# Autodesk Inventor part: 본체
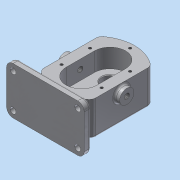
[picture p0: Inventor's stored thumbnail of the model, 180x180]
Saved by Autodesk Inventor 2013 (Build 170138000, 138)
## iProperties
Created: 2019-03
Part Number: 본체
Material: 알루미늄 6061
Document SubType Name: Modeling
Designer: dgall
Density: 1 g/cm^3
Author: dgall
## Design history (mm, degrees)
sketch "스케치1"
  geometry: L1 (-40, -15.279)-(-40, -104.721); L2 (40, -15.279)-(40, -104.721); A1 r 60 centre (0, -60) between (40, -15.279) and (-40, -15.279); A2 r 60 centre (0, -60) between (-40, -104.721) and (40, -104.721); 1 further point
  constraints: 6 point on circle, 4 end point, 2 centre point, 1 coincident, 1 concentric, 1 parallel, 1 vertical, 1 vertical alignment
  dimensions: "d5" = 60 radius of A1; "d7" = 80 distance between parallel lines of L2 L1
extrude "돌출1" new body sketch "스케치1" stored distance "d8" = 53; taper "d9" = 0 deg
sketch "스케치2"
  geometry: L1 (40, -104.721)-(40, -15.279) reference; L2 (-24, -38)-(-24, -82); L3 (24, -38)-(24, -82); A1 r 60 centre (0, -60) between (40, -15.279) and (-40, -15.279) reference; A2 r 24 centre (0, -38) between (24, -38) and (-24, -38); A3 r 24 centre (0, -82) between (-24, -82) and (24, -82); 1 further point
  constraints: 4 end point, 4 point on circle, 3 vertical alignment, 2 centre point, 2 tangent, 1 equal radius, 1 parallel, 1 vertical
  dimensions: "d10" = 24 radius of A2; "d12" = 22 distance of A2.centre A1.centre; "d13" = 22 distance of A3.centre A1.centre
extrude "돌출2" cut sketch "스케치2" distance "d14" = 29; taper "d15" = 0 deg
sketch "스케치3"
  geometry: C1 r 19 at (0, -38); A1 r 60 centre (0, -60) between (40, -15.279) and (-40, -15.279) reference; 1 further point
  constraints: 1 centre point, 1 vertical alignment
  dimensions: "d16" = 38 diameter of C1; "d17" = 22 distance of A1.centre C1.centre
extrude "돌출3" join sketch "스케치3" distance "d18" = 17; taper "d19" = 0 deg
sketch "스케치4"
  geometry: L1 (-14, -2.5)-(-14, 26.5) reference; L2 (-14, 26.5)-(0, 26.5) reference; L3 (0, 26.5)-(0, -26.5) reference; L4 (0, -26.5)-(-19, -26.5) reference; L5 (-19, -26.5)-(-19, -43.5) reference; L6 (-19, -43.5)-(-57, -43.5) reference; L7 (-57, -43.5)-(-57, -26.5) reference; L8 (-57, -26.5)-(-120, -26.5) reference; L9 (-120, -26.5)-(-120, 26.5) reference; L10 (-120, 26.5)-(-106, 26.5) reference; L11 (-106, 26.5)-(-106, -2.5) reference; L12 (-106, -2.5)-(-14, -2.5) reference; L13 (-38, -2.5)-(-14, -2.5) reference; L14 (-38, -2.5)-(-38, -43.5); L15 (-25.5, -2.5)-(-25.5, -17.5); L16 (-25.5, -17.5)-(-29.5, -17.5); L17 (-29.5, -17.5)-(-29.5, -36.2); L18 (-29.5, -36.2)-(-24, -36.2); L19 (-24, -36.2)-(-24, -43.5); 1 further point
  constraints: 12 end point, 4 perpendicular, 3 point on line, 2 parallel, 1 midpoint
  dimensions: "d20" = 19 distance from line of L14.end L5; "d22" = 25 diameter of L15 L14; "d23" = 17 diameter of L17 L14; "d24" = 28 diameter of L19 L14; "d25" = 15 distance of L15.start L15.end; "d26" = 7.3 distance of L18.end L19.end
revolve "회전1" sketch "스케치4" stored, may be unused: angle "d27" = 90 deg
sketch "스케치5"
  geometry: C1 r 12.5 at (0, -82); A1 r 24 centre (0, -82) between (-24, -82) and (24, -82) reference; 1 further point
  constraints: 1 centre point, 1 coincident
  dimensions: "d30" = 25 diameter of C1
extrude "돌출4" cut sketch "스케치5" distance "d32" = 15; taper "d33" = 0 deg
sketch "스케치6"
  geometry: L1 (0, 0)-(0, 89.443) reference; L2 (70, 47.721)-(70, 85.721) reference; L3 (70, 66.721)-(0, 66.721); L4 (0, 66.721)-(29, 66.721) reference; C1 r 11 at (14, 44.721); 1 further point
  constraints: 2 end point, 1 centre point, 1 collinear, 1 midpoint
  dimensions: "d34" = 22 diameter of C1; "d36" = 14 distance from line of C1.centre L1; "d37" = 22 distance from line of C1.centre L3
extrude "돌출5" join sketch "스케치6" distance "d38" = 8; taper "d39" = 0 deg
node "작업 평면1"
hole "구멍1" diameter "d42" = 8.376; stored, may be unused: countersink angle "d46" = 90 deg, drill point angle "d48" = 118 deg; dims "d40" = 10, "d41" = 10, "d43" = 6, "d44" = 4, "d45" = 2, "d47" = 8
node "작업 평면2"
sketch "스케치7"
  geometry: L1 (60, 46.5)-(-60, 46.5); L2 (-60, 46.5)-(-60, -26.5); L3 (-60, -26.5)-(60, -26.5); L4 (60, -26.5)-(60, 46.5); L5 (-40, -26.5)-(40, -26.5) reference; 4 further points
  constraints: 8 end point, 3 midpoint, 2 parallel, 1 horizontal, 1 horizontal alignment, 1 perpendicular, 1 vertical alignment
  dimensions: "d50" = 73 distance of L3.end L1.start; "d52" = 120 distance of L1.start L1.end
extrude "돌출6" join sketch "스케치7" distance "d53" = 10; taper "d54" = 0 deg
fillet "모깎기1" dims "d55" = 10
sketch "스케치8"
  geometry: C1 r 4.5 at (-50, -36.5); A1 r 10 centre (-50, -36.5) between (-60, -36.5) and (-50, -46.5) reference; 1 further point
  constraints: 1 centre point, 1 coincident
  dimensions: "d56" = 9 diameter of C1
extrude "돌출7" cut sketch "스케치8" distance "d57" = 10; taper "d58" = 0 deg
sketch "스케치9"
  geometry: L1 (40, -104.721)-(40, -15.279) reference; L2 (-6, -119.699)-(-6, -128); L3 (6, -119.699)-(6, -128); L4 (-50, -128)-(50, -128) reference; C1 r 19 at (0, -38) reference; A1 r 60 centre (0, -60) between (-40, -104.721) and (40, -104.721) reference; A2 r 60 centre (0, -60) between (-40, -104.721) and (40, -104.721) reference; 1 further point
  constraints: 4 end point, 4 point on circle, 2 parallel, 2 point on line
  dimensions: "d65" = 6 distance from line of L2 C1.centre; "d66" = 12 distance between parallel lines of L3 L2
extrude "돌출8" join sketch "스케치9" distance "d67" = 43; taper "d68" = 0 deg
sketch "스케치10"
  geometry: A1 r 24 centre (0, -38) between (24, -38) and (-24, -38) reference; 2 further points
  constraints: 1 vertical alignment
  dimensions: "d69" = 31 distance of A1.centre point (0, -7)
hole "구멍2" sketch "스케치10" at (0, -7) diameter "d70" = 4.134; stored, may be unused: countersink angle "d74" = 90 deg, drill point angle "d76" = 118 deg; dims "d71" = 10, "d72" = 4, "d73" = 2, "d75" = 12
fillet "모깎기2" dims "d77" = 3
fillet "모깎기3" dims "d78" = 3
fillet "모깎기4" dims "d79" = 3
fillet "모깎기5" dims "d80" = 3
fillet "모깎기6" dims "d81" = 10
fillet "모깎기7" dims "d82" = 3
fillet "모깎기8" dims "d83" = 3
chamfer "모따기1" distance "d84" = 0.7; stored, may be unused: second distance "d85" = 2, angle "d86" = 30 deg
fillet "모깎기9" dims "d87" = 0.5
chamfer "모따기2" distance "d88" = 1; stored, may be unused: second distance "d89" = 2, angle "d90" = 30 deg
sketch "스케치11"
  geometry: C1 r 2.067 at (0, -7) reference; A1 r 24 centre (0, -82) between (-24, -82) and (24, -82) reference; 2 further points
  constraints: 1 vertical alignment
  dimensions: "d91" = 106 distance of point (0, -113) C1.centre
hole "구멍3" sketch "스케치11" at (0, -113) diameter "d92" = 4.134; stored, may be unused: countersink angle "d96" = 90 deg, drill point angle "d98" = 118 deg; dims "d93" = 10, "d94" = 4, "d95" = 2, "d97" = 12
sketch "스케치12"
  geometry: A1 r 60 centre (0, -60) between (36, -12) and (-36, -12) reference; A2 r 24 centre (0, -38) between (24, -38) and (-24, -38) reference; 5 further points
  constraints: 2 horizontal alignment, 2 vertical alignment
  dimensions: "d99" = 31 distance of point (-31, -38) A2.centre; "d100" = 31 distance of point (31, -38) A2.centre; "d101" = 22 vertical distance of A1.centre point (-31, -38); "d102" = 22 vertical distance of point (-31, -82) A1.centre
hole "구멍4" sketch "스케치12" at (-31, -38), (31, -38), (-31, -82), (31, -82) diameter "d103" = 4.134; stored, may be unused: countersink angle "d107" = 90 deg, drill point angle "d109" = 118 deg; dims "d104" = 10, "d105" = 4, "d106" = 2, "d108" = 12
sketch "스케치13"
  geometry: L1 (-50, -46.5)-(50, -46.5) reference; L2 (-60, 16.5)-(-60, -36.5) reference; 2 further points
  constraints: 1 other
  dimensions: "d110" = 10 distance from line of L1 point (0, -36.5); "d111" = 60 distance from line of point (0, -36.5) L2
feature "엠보싱1" sketch "스케치13" dims "d5" = 60, "d7" = 80, "d112" = 0.5, "d113" = 0
node "솔리드1"
mirror "대칭1"
mirror "대칭2"
pattern_linear "직사각형 패턴1" dims "d61" = 53
node "절단 모서리 투영1"
other parameters: "d49" = -138
